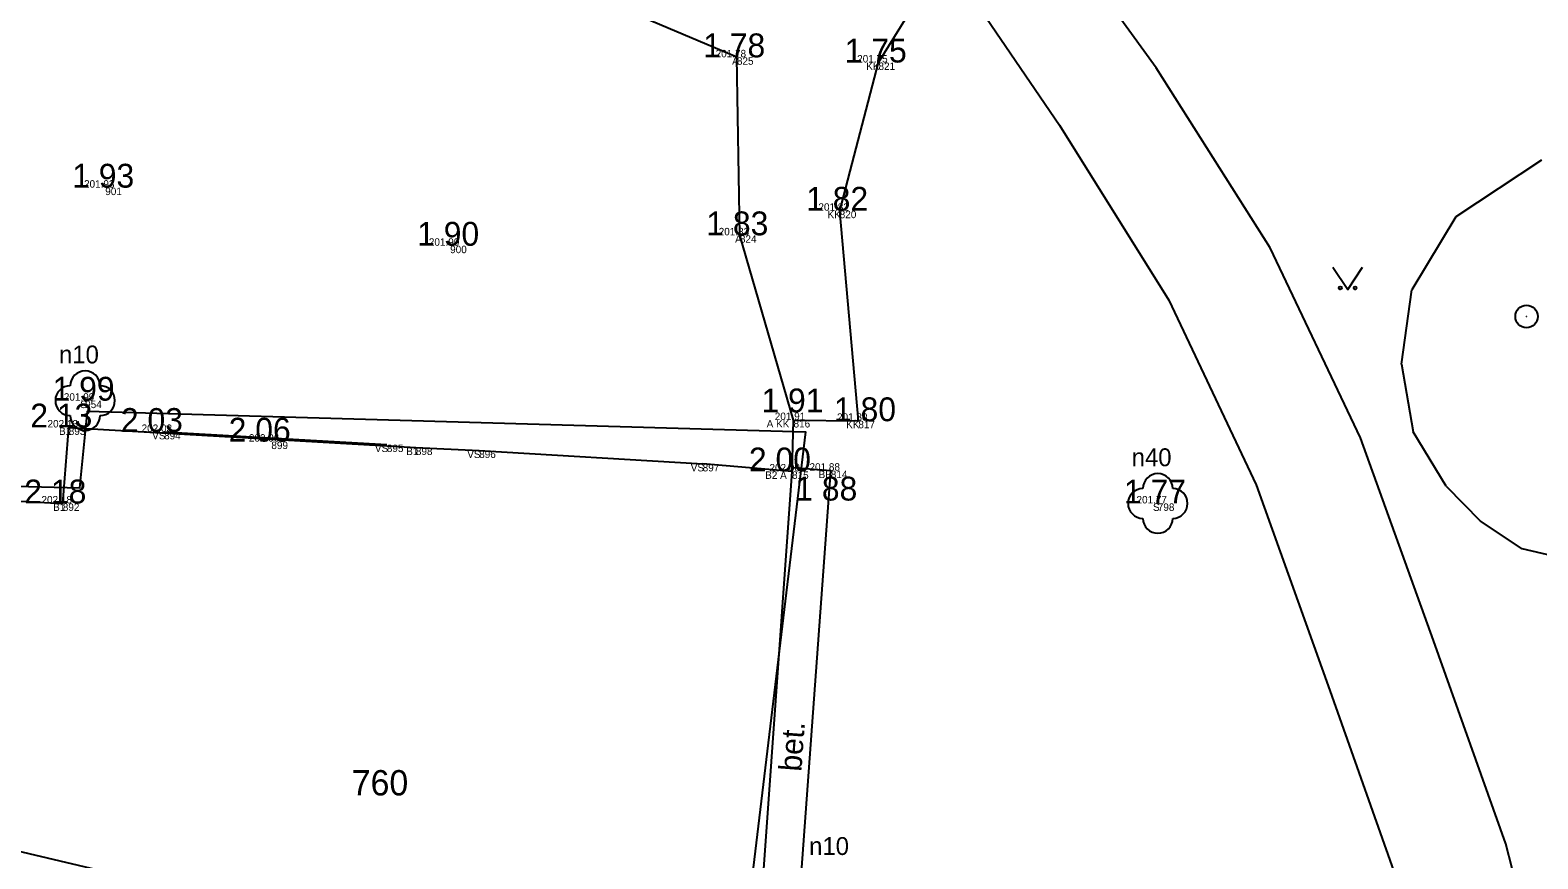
# Model space of a CAD drawing. Extents: x -599717 to -599336, y -1161826 to -1161587.
# Drawn here: x -599503.18 to -599482.94, y -1161678.59 to -1161667.47 of the extents above; entities that cross this region are included whole.
import ezdxf

# ---------------------------------------------------------------- set-up
doc = ezdxf.new("R2010")
doc.units = 0
for name, color, linetype in [('BODY', 7, 'Continuous'), ('BODY_CISLA', 7, 'Continuous'), ('BODY_KODY', 7, 'Continuous'), ('BODY_POLYGONY', 7, 'Continuous'), ('BODY_VYSKY_CELE', 7, 'Continuous'), ('G_BUDOVY', 7, 'Continuous'), ('G_POLOHOPIS', 7, 'Continuous'), ('G_TEXTY', 7, 'Continuous'), ('G_VSTUPY', 7, 'Continuous'), ('G_ZELEN', 7, 'Continuous'), ('G_ZNACKY', 7, 'Continuous'), ('H_KOTY_VYSKOVE', 7, 'Continuous'), ('KN_Hranice parcel', 7, 'Continuous'), ('KN_Parcelní čísla', 7, 'Continuous'), ('KN_Vnitřní kresba', 7, 'Continuous')]:
    doc.layers.add(name, color=color, linetype=linetype)

msp = doc.modelspace()

# ---------------------------------------------------------------- linework, layer by layer
at = {"layer": 'BODY'}
for p, q in [((-599493.69, -1161667.83), (-599493.69, -1161667.83)), ((-599491.79, -1161667.9), (-599491.79, -1161667.9)), ((-599502.17, -1161669.58), (-599502.17, -1161669.58)), ((-599492.31, -1161669.89), (-599492.31, -1161669.89)), ((-599493.65, -1161670.22), (-599493.65, -1161670.22)), ((-599497.54, -1161670.36), (-599497.54, -1161670.36)), ((-599502.44, -1161672.44), (-599502.44, -1161672.44)), ((-599492.93, -1161672.7), (-599492.93, -1161672.7)), ((-599492.06, -1161672.71), (-599492.06, -1161672.71)), ((-599502.66, -1161672.8), (-599502.66, -1161672.8)), ((-599501.38, -1161672.86), (-599501.38, -1161672.86)), ((-599499.94, -1161672.99), (-599499.94, -1161672.99)), ((-599498.39, -1161673.03), (-599498.39, -1161673.03)), ((-599498, -1161673.07), (-599498, -1161673.07)), ((-599497.15, -1161673.11), (-599497.15, -1161673.11)), ((-599494.15, -1161673.29), (-599494.15, -1161673.29)), ((-599492.43, -1161673.38), (-599492.43, -1161673.38)), ((-599492.95, -1161673.39), (-599492.95, -1161673.39)), ((-599502.74, -1161673.82), (-599502.74, -1161673.82)), ((-599488.04, -1161673.82), (-599488.04, -1161673.82))]:
    msp.add_line(p, q, dxfattribs=at)
at = {"layer": 'BODY_POLYGONY'}
for radius in [0.15, 0.0002]:
    msp.add_circle((-599483.09, -1161671.31), radius, dxfattribs=at)
at = {"layer": 'G_BUDOVY'}
for points in [[(-599507.92, -1161678.12), (-599508.87, -1161677.92), (-599508.7, -1161673.5), (-599502.74, -1161673.82), (-599502.66, -1161672.8), (-599498, -1161673.07), (-599497.15, -1161673.11)], [(-599493.503, -1161681.178), (-599492.95, -1161673.39), (-599494.15, -1161673.29)]]:
    msp.add_lwpolyline(points, dxfattribs=at)
at = {"layer": 'G_POLOHOPIS'}
for points in [[(-599492.95, -1161673.39), (-599492.93, -1161672.7), (-599493.65, -1161670.22), (-599493.69, -1161667.83), (-599496.37, -1161666.69), (-599500.66, -1161663.06), (-599501.92, -1161661.81), (-599502.1, -1161661.46)], [(-599492.949, -1161680.483), (-599492.43, -1161673.38), (-599492.949, -1161673.342)]]:
    msp.add_lwpolyline(points, dxfattribs=at)
at = {"layer": 'G_VSTUPY'}
for points in [[(-599501.38, -1161672.86), (-599498.39, -1161673.03)], [(-599497.15, -1161673.11), (-599494.15, -1161673.29)]]:
    msp.add_lwpolyline(points, dxfattribs=at)
at = {"layer": 'G_ZELEN'}
msp.add_lwpolyline([(-599492.93, -1161672.7), (-599492.06, -1161672.71), (-599492.31, -1161669.89), (-599491.79, -1161667.9), (-599489.77, -1161664.64), (-599491.23, -1161662.53), (-599493.42, -1161662.83), (-599496.55, -1161663.05), (-599499.05, -1161662.75), (-599500.66, -1161663.06)], dxfattribs=at)
for centre in [(-599502.44, -1161672.44), (-599488.04, -1161673.82)]:
    msp.add_circle(centre, 0.0002, dxfattribs=at)
for centre, start, end in [((-599502.44, -1161672.24), 0, 180), ((-599502.64, -1161672.44), 90, 270), ((-599502.24, -1161672.44), 270, 90), ((-599502.44, -1161672.64), 180, 360), ((-599488.04, -1161673.62), 0, 180), ((-599488.24, -1161673.82), 90, 270), ((-599487.84, -1161673.82), 270, 90), ((-599488.04, -1161674.02), 180, 360)]:
    msp.add_arc(centre, 0.2, start, end, dxfattribs=at)
at = {"layer": 'G_ZNACKY'}
msp.add_lwpolyline([(-599485.69, -1161670.646), (-599485.49, -1161670.946), (-599485.29, -1161670.646)], dxfattribs=at)
for centre in [(-599485.59, -1161670.926), (-599485.39, -1161670.926)]:
    msp.add_circle(centre, 0.02, dxfattribs=at)
at = {"layer": 'KN_Hranice parcel'}
for points in [[(-599512.86, -1161673.31), (-599508.36, -1161673.46), (-599502.51, -1161673.61), (-599502.41, -1161672.58), (-599492.77, -1161672.86), (-599493.72, -1161680.76)], [(-599512.9, -1161674.85), (-599508.44, -1161677.28), (-599493.72, -1161680.76)]]:
    msp.add_lwpolyline(points, dxfattribs=at)
at = {"layer": 'KN_Vnitřní kresba'}
for p, q in [((-599488.06, -1161667.97), (-599489.96, -1161665.36)), ((-599490.56, -1161666.98), (-599489.36, -1161668.74)), ((-599486.53, -1161670.39), (-599488.06, -1161667.97)), ((-599489.36, -1161668.74), (-599487.89, -1161671.09)), ((-599482.89, -1161669.21), (-599484.04, -1161669.97)), ((-599484.04, -1161669.97), (-599484.63, -1161670.95)), ((-599485.32, -1161672.94), (-599486.53, -1161670.39)), ((-599484.77, -1161671.95), (-599484.63, -1161670.95)), ((-599487.89, -1161671.09), (-599486.72, -1161673.57)), ((-599484.77, -1161671.95), (-599484.61, -1161672.86)), ((-599484.34, -1161675.66), (-599485.32, -1161672.94)), ((-599484.17, -1161673.59), (-599484.61, -1161672.86)), ((-599486.72, -1161673.57), (-599485.73, -1161676.33)), ((-599484.17, -1161673.59), (-599483.71, -1161674.06)), ((-599483.15, -1161674.43), (-599483.71, -1161674.06)), ((-599482.26, -1161674.64), (-599483.15, -1161674.43)), ((-599483.37, -1161678.39), (-599484.34, -1161675.66)), ((-599485.73, -1161676.33), (-599484.75, -1161679.1)), ((-599482.07, -1161683.43), (-599483.37, -1161678.39))]:
    msp.add_line(p, q, dxfattribs=at)

# ---------------------------------------------------------------- texts
at = {"layer": 'BODY_CISLA'}
for s, p in [('825', (-599493.69, -1161667.93)), ('821', (-599491.79, -1161668)), ('901', (-599502.17, -1161669.68)), ('820', (-599492.31, -1161669.99)), ('824', (-599493.65, -1161670.32)), ('900', (-599497.54, -1161670.46)), ('954', (-599502.44, -1161672.54)), ('816', (-599492.93, -1161672.8)), ('817', (-599492.06, -1161672.81)), ('893', (-599502.66, -1161672.9)), ('894', (-599501.38, -1161672.96)), ('899', (-599499.94, -1161673.09)), ('895', (-599498.39, -1161673.13)), ('898', (-599498, -1161673.17)), ('896', (-599497.15, -1161673.21)), ('897', (-599494.15, -1161673.39)), ('814', (-599492.43, -1161673.48)), ('815', (-599492.95, -1161673.49)), ('892', (-599502.74, -1161673.92)), ('798', (-599488.04, -1161673.92))]:
    msp.add_text(s, height=0.1, dxfattribs=at).set_placement(p)
at = {"layer": 'BODY_KODY'}
for s, p in [('A', (-599493.755, -1161667.93)), ('KK', (-599491.954, -1161668)), ('KK', (-599492.474, -1161669.99)), ('A', (-599493.715, -1161670.32)), ('S', (-599502.505, -1161672.54)), ('A KK', (-599493.291, -1161672.8)), ('KK', (-599492.224, -1161672.81)), ('B1', (-599502.79, -1161672.9)), ('VS', (-599501.54, -1161672.96)), ('VS', (-599498.55, -1161673.13)), ('B1', (-599498.13, -1161673.17)), ('VS', (-599497.31, -1161673.21)), ('VS', (-599494.31, -1161673.39)), ('BE', (-599492.594, -1161673.48)), ('B2 A', (-599493.311, -1161673.49)), ('B1', (-599502.87, -1161673.92)), ('S', (-599488.105, -1161673.92))]:
    msp.add_text(s, height=0.1, dxfattribs=at).set_placement(p)
at = {"layer": 'BODY_VYSKY_CELE'}
for s, p in [('201.78 ', (-599493.976, -1161667.83)), ('201.75 ', (-599492.076, -1161667.9)), ('201.93 ', (-599502.455, -1161669.58)), ('201.82 ', (-599492.596, -1161669.89)), ('201.83 ', (-599493.935, -1161670.22)), ('201.90 ', (-599497.826, -1161670.36)), ('201.99 ', (-599502.726, -1161672.44)), ('202.13 ', (-599502.945, -1161672.8)), ('202.03 ', (-599501.682, -1161672.86)), ('201.91 ', (-599493.182, -1161672.7)), ('201.80 ', (-599492.346, -1161672.71)), ('202.06 ', (-599500.242, -1161672.99)), ('202.00 ', (-599493.253, -1161673.39)), ('201.88 ', (-599492.716, -1161673.38)), ('202.18 ', (-599503.026, -1161673.82)), ('201.77 ', (-599488.326, -1161673.82))]:
    msp.add_text(s, height=0.1, dxfattribs=at).set_placement(p)
at = {"layer": 'G_TEXTY'}
for s, p in [('n10', (-599502.791, -1161671.94)), ('n40', (-599488.391, -1161673.32)), ('n10', (-599492.721, -1161678.54))]:
    msp.add_text(s, height=0.24, dxfattribs=at).set_placement(p)
msp.add_text('bet.', height=0.3, rotation=85.8173, dxfattribs=at).set_placement((-599492.826, -1161677.426))
at = {"layer": 'H_KOTY_VYSKOVE'}
for s, p in [(' 1 78', (-599494.262, -1161667.83)), (' 1 75', (-599492.362, -1161667.9)), (' 1 93', (-599502.733, -1161669.58)), (' 1 82', (-599492.88, -1161669.89)), (' 1 83', (-599494.22, -1161670.22)), (' 1 90', (-599498.102, -1161670.36)), (' 1 99', (-599502.996, -1161672.44)), (' 1 91', (-599493.48, -1161672.597)), (' 2 13', (-599503.295, -1161672.8)), (' 2 03', (-599502.079, -1161672.86)), (' 1 80', (-599492.506, -1161672.716)), (' 2 06', (-599500.632, -1161672.99)), (' 2 00', (-599493.648, -1161673.39)), (' 2 18', (-599503.375, -1161673.82)), (' 1 88', (-599493.026, -1161673.781)), (' 1 77', (-599488.613, -1161673.82))]:
    msp.add_text(s, height=0.32, dxfattribs=at).set_placement(p)
at = {"layer": 'KN_Parcelní čísla'}
msp.add_text('760', height=0.34, dxfattribs=at).set_placement((-599498.861, -1161677.74))

doc.saveas('drawing.dxf')
